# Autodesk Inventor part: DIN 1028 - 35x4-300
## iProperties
IsCustomPart: 1
Created: 2006-02
Part Number: DIN 1028 - 35x4-300
Cost Center: 0,97 kg
Material: Stahl, weich, unlegiert
Description: Warmgewalzte gleichschenklinge L-Profile
Document SubType Name: Modeling
Standard: DIN 1028
Designer: E. Rappsilber
Authority: 123036,6 mm^3
Standards Organization: DIN
Language: de-DE
Size Designation: 35x4-300
Categories: <MemberInstance><Categories><Category DisplayName="Profilstahle" InternalName="089c4875-fa83-4c05-b084-43b9cc11f5ed" Mnemonic="GRDR"><CategoryParameter DisplayN
Stock Number: 35x4
SaveDate: 2006-11-14
SaveTime: 13:10
FileName: 35x4-300
GesamtGewicht: 0,97 kg
GesamtVolumen: 123036,6 mm^3
Author: E. Rappsilber
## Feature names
1. Extrusion1
2. Rundung1 [Fillet]
3. Rundung2 [Fillet]
4. Extrusion2
